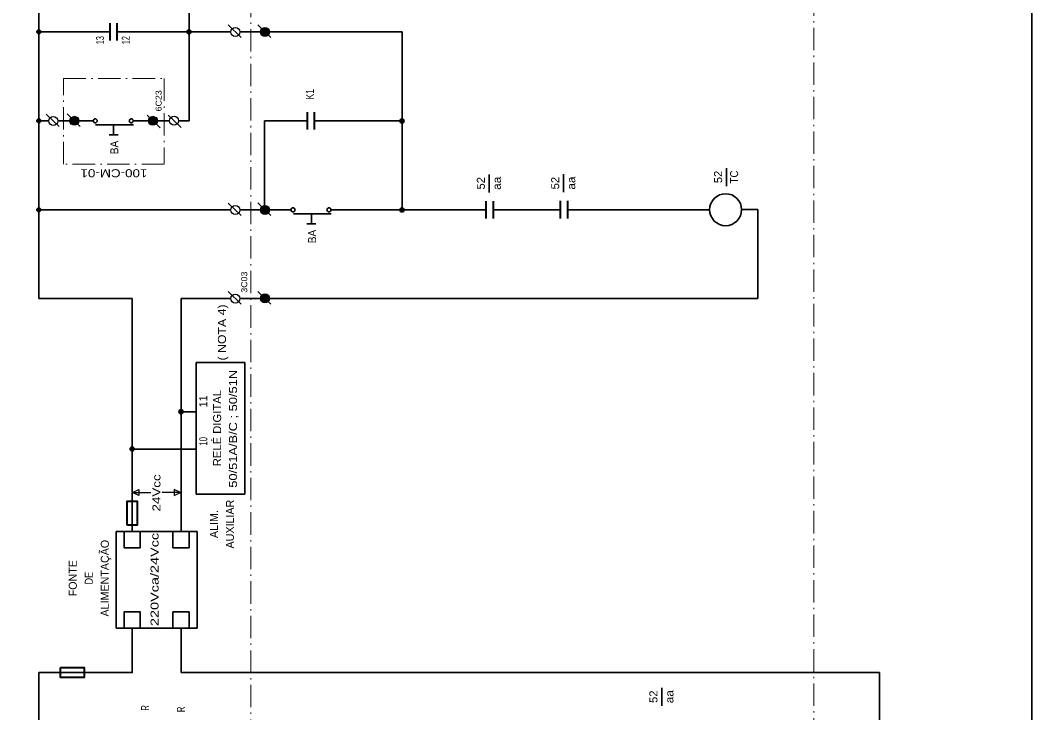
# Model space of a CAD drawing. Extents: x -4160 to -2690, y -474 to 714.
# Drawn here: x -3877.1 to -3750.8, y -67.8 to 18.7 of the extents above; entities that cross this region are included whole.
import ezdxf
from ezdxf.enums import TextEntityAlignment as Align

# ---------------------------------------------------------------- set-up
doc = ezdxf.new("R2010")
doc.units = 0
doc.header["$LTSCALE"] = 0.56
doc.linetypes.add('DOT_DASHED', pattern=[7.7, 5, -1.2, 0.3, -1.2])
for name, color, linetype, lineweight in [('1', 7, 'Continuous', 25), ('2', 7, 'Continuous', 25), ('4', 7, 'Continuous', 25), ('5', 7, 'Continuous', 35)]:
    doc.layers.add(name, color=color, linetype=linetype, lineweight=lineweight)

msp = doc.modelspace()

# ---------------------------------------------------------------- hatches: boundary and pattern name
at = {"layer": '1'}
for points in [[(-3846.5452, 16.7201, 1), (-3846.5452, 17.844, 1)], [(-3874.7922, 17.5465, 1), (-3874.7922, 17.0308, 1)], [(-3856.0328, 17.5465, 1), (-3856.0328, 17.0308, 1)], [(-3874.7922, 6.425, 1), (-3874.7922, 5.9093, 1)], [(-3870.3464, 5.6052, 1), (-3870.3464, 6.7291, 1)], [(-3860.5471, 6.7291, 1), (-3860.5471, 5.6052, 1)], [(-3829.4214, 6.4168, 1), (-3829.4214, 5.9011, 1)], [(-3874.7921, -4.6964, 1), (-3874.7921, -5.2121, 1)], [(-3846.5452, -5.5228, 1), (-3846.5452, -4.3989, 1)], [(-3829.4214, -4.7047, 1), (-3829.4214, -5.2204, 1)], [(-3846.5452, -16.5921, 1), (-3846.5452, -15.4683, 1)], [(-3857.0325, -29.9316, 1), (-3857.0325, -30.4473, 1)], [(-3863.133, -34.5906, 1), (-3863.133, -35.1063, 1)]]:
    msp.add_hatch(color=256, dxfattribs=at).paths.add_polyline_path(points)

# ---------------------------------------------------------------- linework, layer by layer
at = {"layer": '1', "lineweight": 35}
for p, q in [((-3874.7921, -16.04), (-3874.7921, 28.3953)), ((-3856.0327, 6.1671), (-3856.0327, 28.3953)), ((-3851.1361, 18.1419), (-3849.513, 16.5683)), ((-3847.4407, 18.1517), (-3845.8177, 16.5781)), ((-3874.7921, 17.2886), (-3865.9007, 17.2886)), ((-3864.9927, 17.2886), (-3850.8025, 17.2886)), ((-3849.6787, 17.2804), (-3829.4214, 17.2804)), ((-3829.4214, -4.9625), (-3829.4214, 17.2804)), ((-3873.8946, 7.0204), (-3872.2715, 5.4468)), ((-3871.2419, 7.0367), (-3869.6189, 5.4631)), ((-3859.6515, 5.2975), (-3861.2746, 6.8711)), ((-3856.9989, 5.3139), (-3858.6219, 6.8875)), ((-3874.7921, 6.1671), (-3873.5509, 6.1671)), ((-3872.4341, 6.1671), (-3868.0028, 6.1671)), ((-3867.7055, 5.6605), (-3862.978, 5.6605)), ((-3865.9007, 5.6605), (-3864.9927, 5.6605)), ((-3865.4467, 5.6605), (-3865.4467, 4.4072)), ((-3858.4595, 6.1671), (-3863.0029, 6.1671)), ((-3856.0327, 6.1671), (-3857.3425, 6.1671)), ((-3846.6227, 6.1589), (-3841.2522, 6.1589)), ((-3846.6227, -4.5345), (-3846.6227, 6.1589)), ((-3829.4214, 6.1589), (-3840.3442, 6.1589)), ((-3866.0114, 4.4072), (-3864.8821, 4.4072)), ((-3788.8891, -1.9851), (-3788.8891, 0.2574)), ((-3818.5241, -2.7728), (-3818.5241, -0.5303)), ((-3809.2369, -2.7508), (-3809.2369, -0.5083)), ((-3874.7921, -4.9543), (-3850.8025, -4.9543)), ((-3851.1361, -4.1011), (-3849.513, -5.6747)), ((-3843.2995, -4.9625), (-3849.6786, -4.9625)), ((-3847.4407, -4.0913), (-3845.8177, -5.6649)), ((-3818.9003, -4.9625), (-3838.2998, -4.9625)), ((-3809.6131, -4.9405), (-3817.9923, -4.9405)), ((-3808.7051, -4.9405), (-3791.0055, -4.9405)), ((-3787.0075, -4.9185), (-3784.9704, -4.9185)), ((-3784.9703, -16.04), (-3784.9704, -4.9185)), ((-3843.0023, -5.4609), (-3838.2748, -5.4609)), ((-3840.7435, -5.4609), (-3840.7435, -6.7142)), ((-3841.3082, -6.7142), (-3840.1789, -6.7142)), ((-3847.4407, -15.1606), (-3845.8177, -16.7342)), ((-3874.7921, -16.04), (-3863.1329, -16.04)), ((-3863.1329, -45.1617), (-3863.1329, -16.04)), ((-3857.0325, -45.1617), (-3857.0325, -16.04)), ((-3857.0325, -16.04), (-3850.8024, -16.04)), ((-3851.136, -15.1704), (-3849.5129, -16.744)), ((-3849.6785, -16.04), (-3784.9703, -16.04)), ((-3857.0325, -30.1895), (-3855.1293, -30.1895)), ((-3863.1329, -34.8485), (-3855.1293, -34.8485)), ((-3857.0325, -62.7685), (-3857.0325, -57.2131)), ((-3874.7921, -141.8757), (-3874.7921, -62.7685)), ((-3857.0325, -62.7685), (-3769.7833, -62.7685)), ((-3769.7833, -62.7685), (-3769.7833, -141.8757)), ((-3796.9667, -66.9269), (-3796.9667, -64.6843))]:
    msp.add_line(p, q, dxfattribs=at)
at = {"layer": '1', "lineweight": 40}
for p, q in [((-3865.9007, 16.1953), (-3865.9007, 18.3819)), ((-3864.9927, 16.1953), (-3864.9927, 18.3819)), ((-3841.2522, 5.0657), (-3841.2522, 7.2523)), ((-3840.3442, 5.0657), (-3840.3442, 7.2523)), ((-3818.9003, -6.0577), (-3818.9003, -3.8711)), ((-3817.9923, -6.0577), (-3817.9923, -3.8711)), ((-3809.6131, -6.0357), (-3809.6131, -3.8491)), ((-3808.7051, -6.0357), (-3808.7051, -3.8491))]:
    msp.add_line(p, q, dxfattribs=at)
at = {"layer": '1'}
for p, q in [((-3863.0863, -40.2817), (-3860.7972, -40.2817)), ((-3857.0791, -40.2817), (-3859.3682, -40.2817))]:
    msp.add_line(p, q, dxfattribs=at)
at = {"layer": '1', "linetype": 'DOT_DASHED', "lineweight": 13}
for points in [[(-3848.3279, -136.1027), (-3848.3279, 47.9667), (-3777.9927, 47.9667), (-3777.9927, -136.1027)], [(-3871.7061, 0.7529), (-3871.7061, 11.4473), (-3859.1484, 11.4473), (-3859.1484, 0.7529)]]:
    msp.add_lwpolyline(points, close=True, dxfattribs=at)
at = {"layer": '1'}
for points in [[(-3862.2908, -39.9039), (-3862.2908, -40.6597), (-3863.0863, -40.2817)], [(-3857.8746, -39.9039), (-3857.8746, -40.6597), (-3857.0791, -40.2817)]]:
    msp.add_lwpolyline(points, close=True, dxfattribs=at)
at = {"layer": '1', "lineweight": 40}
for points in [[(-3863.7626, -44.3621), (-3863.7626, -41.3743), (-3862.5029, -41.3743), (-3862.5029, -44.3621)], [(-3872.1015, -62.1387), (-3869.1136, -62.1387), (-3869.1136, -63.3983), (-3872.1015, -63.3983)]]:
    msp.add_lwpolyline(points, close=True, dxfattribs=at)
at = {"layer": '1', "lineweight": 35}
msp.add_lwpolyline([(-3874.7921, -62.7685), (-3863.1329, -62.7685), (-3863.1329, -57.2131)], dxfattribs=at)
at = {"layer": '1'}
for centre in [(-3850.2405, 17.2722), (-3846.5452, 17.2821), (-3872.999, 6.1508), (-3870.3464, 6.1672), (-3860.5471, 6.1672), (-3857.8945, 6.1835), (-3850.2405, -4.9707), (-3846.5452, -4.9609), (-3850.2405, -16.04), (-3846.5452, -16.0302)]:
    msp.add_circle(centre, 0.5619, dxfattribs=at)
at = {"layer": '1', "lineweight": 35}
for centre, radius in [((-3874.7922, 17.2886), 0.2579), ((-3856.0328, 17.2886), 0.2579), ((-3874.7922, 6.1672), 0.2579), ((-3867.7528, 6.1671), 0.25), ((-3863.2529, 6.1671), 0.25), ((-3829.4214, 6.1589), 0.2579), ((-3789.0064, -4.9405), 1.999), ((-3874.7921, -4.9543), 0.2579), ((-3843.0496, -4.9543), 0.25), ((-3838.5497, -4.9543), 0.25), ((-3829.4214, -4.9625), 0.2579), ((-3857.0325, -30.1895), 0.2579), ((-3863.133, -34.8485), 0.2579)]:
    msp.add_circle(centre, radius, dxfattribs=at)
at = {"layer": '2', "lineweight": 35}
for points in [[(-3855.1293, -40.4635), (-3855.1293, -24.0493), (-3849.0827, -24.0493), (-3849.0827, -40.4635)], [(-3865.1452, -57.2131), (-3865.1452, -45.1617), (-3855.0202, -45.1617), (-3855.0202, -57.2131)], [(-3864.1455, -45.1617), (-3864.1455, -47.1867), (-3862.1205, -47.1867), (-3862.1205, -45.1617)], [(-3856.0199, -45.1617), (-3856.0199, -47.1867), (-3858.0449, -47.1867), (-3858.0449, -45.1617)], [(-3864.1455, -57.2131), (-3864.1455, -55.1881), (-3862.1205, -55.1881), (-3862.1205, -57.2131)], [(-3856.0199, -57.2131), (-3856.0199, -55.1881), (-3858.0449, -55.1881), (-3858.0449, -57.2131)]]:
    msp.add_lwpolyline(points, close=True, dxfattribs=at)
at = {"layer": '5'}
msp.add_lwpolyline([(-3924.7642, -166.52), (-3924.7642, 86.48), (-3750.7642, 86.48), (-3750.7642, -166.52)], close=True, dxfattribs=at)

# ---------------------------------------------------------------- texts
at = {"layer": '1'}
for s, height, width, p in [('13', 1, 0.6, (-3866.6473, 16.2429)), ('12', 1, 0.6, (-3863.4365, 16.2429)), ('6C23', 0.75, 1.1, (-3859.4605, 8.6655)), ('K1', 1, 0.8, (-3840.4329, 9.4877)), ('BA', 1, 0.95, (-3864.8625, 2.8324)), ('52', 1, 1.05, (-3819.0811, -1.6356)), ('aa', 1, 1.1, (-3817.0811, -1.6356)), ('52', 1, 1.05, (-3809.7939, -1.6136)), ('aa', 1, 1.1, (-3807.7939, -1.6136)), ('52', 1, 1.05, (-3789.4461, -0.8479)), ('TC', 1, 0.9, (-3787.4461, -0.8479)), ('BA', 1, 0.95, (-3840.1593, -8.289)), ('3C03', 0.75, 1.1, (-3848.7643, -13.9947)), ('( NOTA 4)', 1, 1.15, (-3851.4189, -20.2777)), ('50/51A/B/C ; 50/51N', 1, 1.2, (-3850.0375, -32.3188)), ('RELÉ DIGITAL', 1, 1.05, (-3852.0234, -32.236)), ('10', 1, 0.65, (-3853.7503, -33.8753)), ('24Vcc', 1, 1.25, (-3859.6019, -40.3308)), ('220Vca/24Vcc', 1, 1.35, (-3859.8388, -51.1387)), ('52', 1, 1.05, (-3797.5235, -65.7897)), ('aa', 1, 1.1, (-3795.5235, -65.7897)), ('R', 1, 0.65, (-3861.0193, -67.1825)), ('R', 1, 0.65, (-3856.5522, -67.3794))]:
    msp.add_text(s, height=height, rotation=90, dxfattribs=dict(at, width=width)).set_placement(p, align=Align.CENTER)
for s, p in [('11', (-3853.7503, -28.8903)), ('AUXILIAR', (-3850.4189, -44.2221)), ('ALIM.', (-3852.4189, -44.2221))]:
    msp.add_text(s, height=1, rotation=90, dxfattribs=at).set_placement(p, align=Align.CENTER)
at = {"layer": '2'}
for s, p in [('ALIMENTAÇÃO', (-3866.0533, -50.9832)), ('FONTE', (-3870.0533, -50.9833))]:
    msp.add_text(s, height=1, rotation=90, dxfattribs=at).set_placement(p, align=Align.CENTER)
at = {"layer": '2', "width": 0.85}
msp.add_text('DE', height=1, rotation=90, dxfattribs=at).set_placement((-3868.0533, -50.9833), align=Align.CENTER)
at = {"layer": '4', "width": 1.25}
msp.add_text('100-CM-01', height=0.9999, rotation=180, dxfattribs=at).set_placement((-3865.4134, 0.1219), align=Align.CENTER)

doc.saveas('drawing.dxf')
